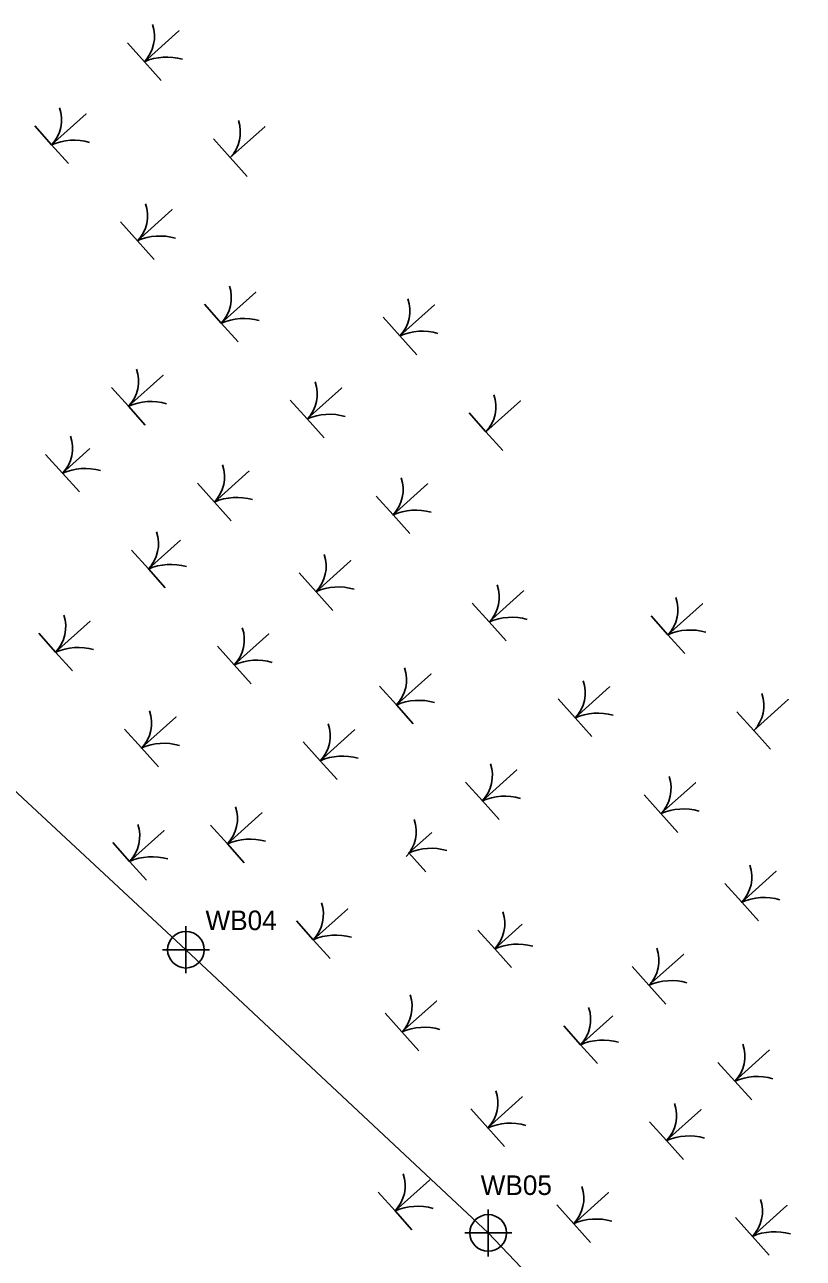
# Model space of a CAD drawing. Extents: x 2126502 to 2127032, y 149550 to 150101.
# Drawn here: x 2126649 to 2126748.5, y 149905.9 to 150063.6 of the extents above; entities that cross this region are included whole.
import ezdxf

# ---------------------------------------------------------------- set-up
doc = ezdxf.new("R2010")
doc.units = 0
for name, color, linetype in [('Exist Environmental Wetland Boundary', 7, 'Continuous'), ('Exist Environmental Wetland Boundary Cogo Number', 7, 'Continuous'), ('Exist Environmental Wetland Boundary Cogo Point CELL', 7, 'Continuous'), ('Exist Hydro Swamp or Marsh', 7, 'Continuous')]:
    doc.layers.add(name, color=color, linetype=linetype)

msp = doc.modelspace()

# ---------------------------------------------------------------- linework, layer by layer
at = {"layer": 'Exist Environmental Wetland Boundary'}
msp.add_lwpolyline([(2126558.24, 150042.64), (2126586.56, 150016.72), (2126627.79, 149984.18), (2126669.56, 149945.39), (2126708.19, 149909.19), (2126734.44, 149881.64), (2126779.81, 149842.99), (2126804.06, 149818.21), (2126812.44, 149808.38)], dxfattribs=at)
at = {"layer": 'Exist Environmental Wetland Boundary Cogo Point CELL'}
for points in [[(2126669.56, 149948.39), (2126669.56, 149945.39)], [(2126666.56, 149945.39), (2126669.56, 149945.39)], [(2126669.56, 149945.39), (2126672.56, 149945.39)], [(2126669.56, 149945.39), (2126669.56, 149942.39)], [(2126708.19, 149912.19), (2126708.19, 149909.19)], [(2126705.19, 149909.19), (2126708.19, 149909.19)], [(2126708.19, 149909.19), (2126711.19, 149909.19)], [(2126708.19, 149909.19), (2126708.19, 149906.19)]]:
    msp.add_lwpolyline(points, dxfattribs=at)
for centre in [(2126669.56, 149945.39), (2126708.19, 149909.19)]:
    msp.add_circle(centre, 2.34, dxfattribs=at)
at = {"layer": 'Exist Hydro Swamp or Marsh'}
for points in [[(2126662.1, 150061.29), (2126664.25, 150058.88), (2126668.66, 150062.83), (2126664.25, 150058.88), (2126666.4, 150056.48)], [(2126650.24, 150050.67), (2126652.39, 150048.26), (2126656.8, 150052.21), (2126652.39, 150048.26), (2126654.54, 150045.86)], [(2126673.07, 150049.03), (2126675.22, 150046.63), (2126679.63, 150050.58), (2126675.22, 150046.63), (2126677.38, 150044.23)], [(2126661.22, 150038.41), (2126663.37, 150036.01), (2126667.78, 150039.96), (2126663.37, 150036.01), (2126665.52, 150033.61)], [(2126671.93, 150027.88), (2126674.08, 150025.48), (2126678.49, 150029.42), (2126674.08, 150025.48), (2126676.23, 150023.07)], [(2126694.76, 150026.25), (2126696.91, 150023.84), (2126701.32, 150027.79), (2126696.91, 150023.84), (2126699.06, 150021.44)], [(2126660.07, 150017.26), (2126662.22, 150014.85), (2126666.63, 150018.8), (2126662.22, 150014.85), (2126664.37, 150012.45)], [(2126682.9, 150015.63), (2126685.06, 150013.22), (2126689.46, 150017.17), (2126685.06, 150013.22), (2126687.21, 150010.82)], [(2126705.74, 150013.99), (2126707.89, 150011.59), (2126712.3, 150015.54), (2126707.89, 150011.59), (2126710.04, 150009.19)], [(2126651.63, 150008.7), (2126653.78, 150006.3), (2126657.3, 150009.45)], [(2126657.3, 150009.45), (2126653.78, 150006.3), (2126655.94, 150003.9)], [(2126671.05, 150005), (2126673.2, 150002.6), (2126677.61, 150006.55), (2126673.2, 150002.6), (2126675.35, 150000.2)], [(2126693.88, 150003.37), (2126696.03, 150000.97), (2126700.44, 150004.92), (2126696.03, 150000.97), (2126698.18, 149998.57)], [(2126662.61, 149996.45), (2126664.76, 149994.05), (2126668.86, 149997.72)], [(2126668.86, 149997.72), (2126664.76, 149994.05), (2126666.91, 149991.64)], [(2126684.04, 149993.55), (2126686.19, 149991.15), (2126690.6, 149995.1), (2126686.19, 149991.15), (2126688.34, 149988.75)], [(2126706.16, 149989.69), (2126708.32, 149987.29), (2126712.72, 149991.24), (2126708.32, 149987.29), (2126710.47, 149984.88)], [(2126729, 149988.06), (2126731.15, 149985.65), (2126735.56, 149989.6), (2126731.15, 149985.65), (2126733.3, 149983.25)], [(2126650.75, 149985.83), (2126652.91, 149983.42), (2126657.31, 149987.37), (2126652.91, 149983.42), (2126655.06, 149981.02)], [(2126673.59, 149984.19), (2126675.74, 149981.79), (2126680.15, 149985.74), (2126675.74, 149981.79), (2126677.89, 149979.39)], [(2126694.31, 149979.07), (2126696.46, 149976.67), (2126700.87, 149980.61), (2126696.46, 149976.67), (2126698.61, 149974.26)], [(2126717.14, 149977.44), (2126719.29, 149975.03), (2126723.7, 149978.98), (2126719.29, 149975.03), (2126721.45, 149972.63)], [(2126739.97, 149975.8), (2126742.13, 149973.4), (2126746.53, 149977.35), (2126742.13, 149973.4), (2126744.28, 149971)], [(2126661.73, 149973.57), (2126663.88, 149971.17), (2126668.29, 149975.12), (2126663.88, 149971.17), (2126666.04, 149968.77)], [(2126684.56, 149971.94), (2126686.72, 149969.54), (2126691.12, 149973.49), (2126686.72, 149969.54), (2126688.87, 149967.14)], [(2126705.28, 149966.81), (2126707.44, 149964.41), (2126711.84, 149968.36), (2126707.44, 149964.41), (2126709.59, 149962.01)], [(2126728.12, 149965.18), (2126730.27, 149962.78), (2126734.68, 149966.73), (2126730.27, 149962.78), (2126732.42, 149960.38)], [(2126672.71, 149961.32), (2126674.86, 149958.92), (2126679.27, 149962.87), (2126674.86, 149958.92), (2126677.01, 149956.51)], [(2126660.21, 149959.08), (2126662.37, 149956.67), (2126666.77, 149960.62), (2126662.37, 149956.67), (2126664.52, 149954.27)], [(2126700.98, 149960.39), (2126698.04, 149957.75), (2126700.2, 149955.35)], [(2126738.43, 149953.86), (2126740.59, 149951.46), (2126744.99, 149955.41), (2126740.59, 149951.46), (2126742.74, 149949.06)], [(2126683.68, 149949.07), (2126685.84, 149946.66), (2126690.24, 149950.61), (2126685.84, 149946.66), (2126687.99, 149944.26)], [(2126706.87, 149947.9), (2126709.02, 149945.5), (2126712.54, 149948.65)], [(2126712.54, 149948.65), (2126709.02, 149945.5), (2126711.17, 149943.1)], [(2126726.58, 149943.24), (2126728.73, 149940.84), (2126733.14, 149944.79), (2126728.73, 149940.84), (2126730.88, 149938.44)], [(2126695.01, 149937.28), (2126697.16, 149934.88), (2126701.57, 149938.83), (2126697.16, 149934.88), (2126699.32, 149932.48)], [(2126717.85, 149935.65), (2126720, 149933.25), (2126724.1, 149936.92)], [(2126724.1, 149936.92), (2126720, 149933.25), (2126722.15, 149930.84)], [(2126737.55, 149930.99), (2126739.71, 149928.58), (2126744.11, 149932.53), (2126739.71, 149928.58), (2126741.86, 149926.18)], [(2126705.99, 149925.03), (2126708.14, 149922.62), (2126712.55, 149926.57), (2126708.14, 149922.62), (2126710.29, 149920.22)], [(2126728.82, 149923.4), (2126730.97, 149920.99), (2126735.38, 149924.94), (2126730.97, 149920.99), (2126733.13, 149918.59)], [(2126694.13, 149914.41), (2126696.29, 149912), (2126700.69, 149915.95), (2126696.29, 149912), (2126698.44, 149909.6)], [(2126716.97, 149912.77), (2126719.12, 149910.37), (2126723.53, 149914.32), (2126719.12, 149910.37), (2126721.27, 149907.97)], [(2126739.8, 149911.14), (2126741.95, 149908.74), (2126746.36, 149912.69), (2126741.95, 149908.74), (2126744.1, 149906.34)]]:
    msp.add_lwpolyline(points, dxfattribs=at)
for centre, radius, start, end in [((2126660.93, 150062.09), 4.61, 315.9957, 19.3903), ((2126667.12, 150052.27), 7.21, 73.9828, 113.4775), ((2126649.07, 150051.47), 4.61, 315.9957, 19.3903), ((2126671.91, 150049.83), 4.61, 315.9957, 19.3903), ((2126655.26, 150041.65), 7.21, 73.9828, 113.4775), ((2126660.05, 150039.21), 4.61, 315.9957, 19.3903), ((2126666.24, 150029.4), 7.21, 73.9828, 113.4775), ((2126670.76, 150028.68), 4.61, 315.9957, 19.3903), ((2126693.59, 150027.05), 4.61, 315.9957, 19.3903), ((2126676.95, 150018.86), 7.21, 73.9828, 113.4775), ((2126699.78, 150017.23), 7.21, 73.9828, 113.4775), ((2126658.9, 150018.06), 4.61, 315.9957, 19.3903), ((2126681.74, 150016.43), 4.61, 315.9957, 19.3903), ((2126704.57, 150014.79), 4.61, 315.9957, 19.3903), ((2126665.09, 150008.24), 7.21, 73.9828, 113.4775), ((2126687.93, 150006.61), 7.21, 73.9828, 113.4775), ((2126650.47, 150009.5), 4.61, 315.9957, 19.3903), ((2126656.66, 149999.69), 7.21, 73.9828, 113.4775), ((2126669.88, 150005.81), 4.61, 315.9957, 19.3903), ((2126692.71, 150004.17), 4.61, 315.9957, 19.3903), ((2126676.07, 149995.99), 7.21, 73.9828, 113.4775), ((2126698.9, 149994.36), 7.21, 73.9828, 113.4775), ((2126661.44, 149997.25), 4.61, 315.9957, 19.3903), ((2126682.87, 149994.36), 4.61, 315.9957, 19.3903), ((2126667.63, 149987.43), 7.21, 73.9828, 113.4775), ((2126689.06, 149984.54), 7.21, 73.9828, 113.4775), ((2126705, 149990.49), 4.61, 315.9957, 19.3903), ((2126727.83, 149988.86), 4.61, 315.9957, 19.3903), ((2126649.59, 149986.63), 4.61, 315.9957, 19.3903), ((2126711.19, 149980.67), 7.21, 73.9828, 113.4775), ((2126672.42, 149985), 4.61, 315.9957, 19.3903), ((2126734.02, 149979.04), 7.21, 73.9828, 113.4775), ((2126655.78, 149976.81), 7.21, 73.9828, 113.4775), ((2126678.61, 149975.18), 7.21, 73.9828, 113.4775), ((2126693.14, 149979.87), 4.61, 315.9957, 19.3903), ((2126715.98, 149978.24), 4.61, 315.9957, 19.3903), ((2126738.81, 149976.6), 4.61, 315.9957, 19.3903), ((2126699.33, 149970.05), 7.21, 73.9828, 113.4775), ((2126660.57, 149974.37), 4.61, 315.9957, 19.3903), ((2126722.16, 149968.42), 7.21, 73.9828, 113.4775), ((2126683.4, 149972.74), 4.61, 315.9957, 19.3903), ((2126666.75, 149964.56), 7.21, 73.9828, 113.4775), ((2126689.59, 149962.93), 7.21, 73.9828, 113.4775), ((2126704.12, 149967.62), 4.61, 315.9957, 19.3903), ((2126726.95, 149965.98), 4.61, 315.9957, 19.3903), ((2126710.31, 149957.8), 7.21, 73.9828, 113.4775), ((2126671.54, 149962.12), 4.61, 315.9957, 19.3903), ((2126733.14, 149956.17), 7.21, 73.9828, 113.4775), ((2126659.05, 149959.88), 4.61, 315.9957, 19.3903), ((2126694.38, 149960.49), 4.61, 315.9957, 19.3903), ((2126677.73, 149952.31), 7.21, 73.9828, 113.4775), ((2126700.92, 149951.14), 7.21, 73.9828, 113.4775), ((2126665.24, 149950.06), 7.21, 73.9828, 113.4775), ((2126737.27, 149954.66), 4.61, 315.9957, 19.3903), ((2126682.52, 149949.87), 4.61, 315.9957, 19.3903), ((2126743.46, 149944.85), 7.21, 73.9828, 113.4775), ((2126705.7, 149948.7), 4.61, 315.9957, 19.3903), ((2126688.71, 149940.05), 7.21, 73.9828, 113.4775), ((2126711.89, 149938.89), 7.21, 73.9828, 113.4775), ((2126725.41, 149944.04), 4.61, 315.9957, 19.3903), ((2126731.6, 149934.23), 7.21, 73.9828, 113.4775), ((2126693.85, 149938.08), 4.61, 315.9957, 19.3903), ((2126716.68, 149936.45), 4.61, 315.9957, 19.3903), ((2126700.04, 149928.27), 7.21, 73.9828, 113.4775), ((2126722.87, 149926.63), 7.21, 73.9828, 113.4775), ((2126736.39, 149931.79), 4.61, 315.9957, 19.3903), ((2126742.58, 149921.97), 7.21, 73.9828, 113.4775), ((2126704.82, 149925.83), 4.61, 315.9957, 19.3903), ((2126727.66, 149924.2), 4.61, 315.9957, 19.3903), ((2126711.01, 149916.01), 7.21, 73.9828, 113.4775), ((2126733.85, 149914.38), 7.21, 73.9828, 113.4775), ((2126692.97, 149915.21), 4.61, 315.9957, 19.3903), ((2126715.8, 149913.58), 4.61, 315.9957, 19.3903), ((2126738.63, 149911.94), 4.61, 315.9957, 19.3903), ((2126699.16, 149905.39), 7.21, 73.9828, 113.4775), ((2126721.99, 149903.76), 7.21, 73.9828, 113.4775), ((2126744.82, 149902.13), 7.21, 73.9828, 113.4775)]:
    msp.add_arc(centre, radius, start, end, dxfattribs=at)

# ---------------------------------------------------------------- texts
at = {"layer": 'Exist Environmental Wetland Boundary Cogo Number'}
for s, p in [('WB04', (2126672.06, 149947.89)), ('WB05', (2126707.23, 149914.04))]:
    msp.add_text(s, height=2.5, dxfattribs=at).set_placement(p)

doc.saveas('drawing.dxf')
